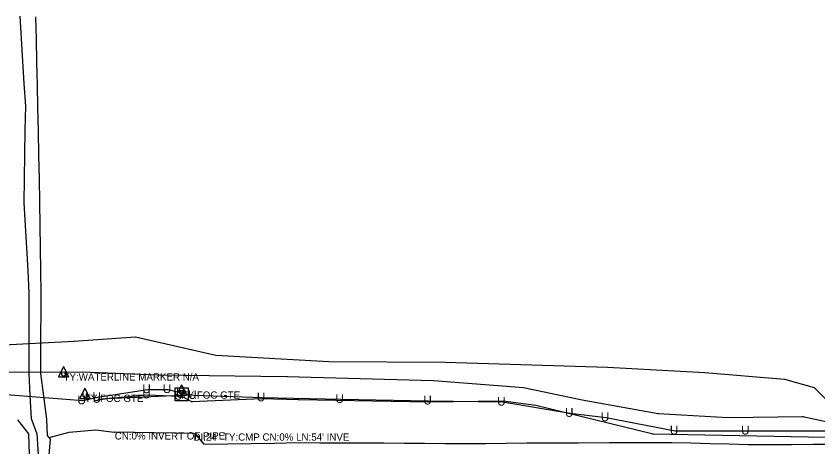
# Model space of a CAD drawing. Extents: x 1800653 to 1804042, y 522635 to 523313.
# Drawn here: x 1802247 to 1802797, y 523018 to 523313 of the extents above; entities that cross this region are included whole.
import ezdxf

# ---------------------------------------------------------------- set-up
doc = ezdxf.new("R2010")
doc.units = 0
for name, color, linetype in [('Default', 7, 'Continuous'), ('S_DITCHLINE', 7, 'Continuous'), ('S_DRG_PT_SYM', 7, 'Continuous'), ('S_FIBER_OPTIC_CABLE', 7, 'Continuous'), ('S_GAS_UTILITIES', 7, 'Continuous'), ('S_SIDE_DRAIN', 7, 'Continuous'), ('S_SIDE_DRAIN_ANNOT', 7, 'Continuous'), ('S_STREAM', 7, 'Continuous'), ('S_TELEPHONE_UTILITIES', 7, 'Continuous'), ('S_UNDERGROUND_CABLE', 7, 'Continuous'), ('S_UTILITY_POLE_ANNOT', 7, 'Continuous'), ('S_UTL_PT_SYM', 7, 'Continuous'), ('S_WATER_UTILITIES', 7, 'Continuous')]:
    doc.layers.add(name, color=color, linetype=linetype)

msp = doc.modelspace()

# ---------------------------------------------------------------- linework, layer by layer
at = {"layer": 'S_DITCHLINE'}
for points in [[(1802269.66, 523024.43), (1802283.4, 523028.06), (1802301.66, 523029.67), (1802314.11, 523027.91)], [(1802369.25, 523027.2), (1802375.66, 523019.66), (1802391.84, 523019.94), (1802408.03, 523020.23), (1802424.22, 523020.51), (1802440.41, 523020.79), (1802455.09, 523020.75), (1802469.77, 523020.7), (1802484.45, 523020.66), (1802499.13, 523020.61), (1802513.07, 523020.5), (1802527.01, 523020.39), (1802540.96, 523020.28), (1802554.9, 523020.18), (1802568.97, 523020.3), (1802583.04, 523020.43), (1802597.12, 523020.56), (1802611.19, 523020.69), (1802632.52, 523020.74), (1802653.86, 523020.8), (1802675.19, 523020.85), (1802696.52, 523020.91), (1802709.66, 523020.57), (1802722.79, 523020.22), (1802735.93, 523019.88), (1802749.06, 523019.54), (1802763.84, 523019.58), (1802778.62, 523019.62), (1802793.4, 523019.66), (1802808.18, 523019.7)]]:
    msp.add_lwpolyline(points, dxfattribs=at)
at = {"layer": 'S_DRG_PT_SYM'}
for points in [[(1802314.54, 523027.95), (1802314.54, 523028), (1802314.54, 523027.95), (1802314.49, 523027.95), (1802314.54, 523027.95), (1802314.54, 523027.9), (1802314.54, 523027.95), (1802314.59, 523027.95)], [(1802368.56, 523027.13), (1802368.56, 523027.18), (1802368.56, 523027.13), (1802368.51, 523027.13), (1802368.56, 523027.13), (1802368.56, 523027.08), (1802368.56, 523027.13), (1802368.61, 523027.13)]]:
    msp.add_lwpolyline(points, dxfattribs=at)
at = {"layer": 'S_FIBER_OPTIC_CABLE'}
for p, q in [((1802309.12, 523050.85), (1802303.42, 523049.88)), ((1802349.78, 523052.63), (1802309.12, 523050.85)), ((1802359.84, 523052.9), (1802349.78, 523052.63)), ((1802367.52, 523048.71), (1802359.84, 523052.9)), ((1802415.11, 523050.82), (1802367.52, 523048.71)), ((1802440.73, 523050.19), (1802415.11, 523050.82)), ((1802529.47, 523048.64), (1802440.73, 523050.19)), ((1802580.88, 523049.27), (1802529.47, 523048.64)), ((1802603.36, 523046.35), (1802580.88, 523049.27)), ((1802683.7, 523026.61), (1802603.36, 523046.35)), ((1802802.2, 523024.23), (1802683.7, 523026.61))]:
    msp.add_line(p, q, dxfattribs=at)
at = {"layer": 'S_GAS_UTILITIES'}
for p, q in [((1802220.06, 523086.97), (1802286.56, 523090.26)), ((1802286.56, 523090.26), (1802328.86, 523093.33)), ((1802328.86, 523093.33), (1802383.84, 523080.76)), ((1802383.84, 523080.76), (1802461.37, 523076.34)), ((1802461.37, 523076.34), (1802541.11, 523075.84)), ((1802541.11, 523075.84), (1802652.53, 523072.49)), ((1802652.53, 523072.49), (1802719.3, 523068.84)), ((1802719.3, 523068.84), (1802773.94, 523064.21)), ((1802773.94, 523064.21), (1802794.31, 523058.67)), ((1802794.31, 523058.67), (1802806.01, 523046.72))]:
    msp.add_line(p, q, dxfattribs=at)
at = {"layer": 'S_SIDE_DRAIN'}
msp.add_line((1802368.56, 523027.13), (1802314.54, 523027.95), dxfattribs=at)
at = {"layer": 'S_STREAM'}
for points in [[(1802249.41, 523313.08), (1802250.37, 523297.65), (1802251.32, 523282.22), (1802252.27, 523266.78), (1802253.23, 523251.35), (1802252.98, 523234.78), (1802252.74, 523218.21), (1802252.5, 523201.64), (1802252.26, 523185.07), (1802253.13, 523169.63), (1802254, 523154.19), (1802254.87, 523138.75), (1802255.74, 523123.32), (1802255.71, 523109.58), (1802255.69, 523095.84), (1802255.67, 523082.1), (1802255.65, 523068.37), (1802256.4, 523052.81), (1802257.15, 523037.26), (1802261.21, 523026.93), (1802262, 523012.39)], [(1802260.22, 523312.47), (1802260.58, 523296.96), (1802260.94, 523281.44), (1802261.29, 523265.92), (1802261.65, 523250.4), (1802261.98, 523234.11), (1802262.31, 523217.81), (1802262.64, 523201.52), (1802262.97, 523185.22), (1802263.18, 523169.68), (1802263.39, 523154.14), (1802263.59, 523138.6), (1802263.8, 523123.06), (1802263.75, 523109.33), (1802263.71, 523095.6), (1802263.66, 523081.86), (1802263.62, 523068.13), (1802265.62, 523052.55), (1802267.63, 523036.97), (1802268.3, 523025.72), (1802270.16, 523023.24), (1802269.12, 523009.76)], [(1802247.74, 523036.5), (1802255.39, 523026.86), (1802255.81, 523012.78), (1802256.24, 522998.7), (1802253.02, 522982.1), (1802249.81, 522965.5), (1802248.85, 522942.84), (1802247.89, 522920.18)]]:
    msp.add_lwpolyline(points, dxfattribs=at)
at = {"layer": 'S_TELEPHONE_UTILITIES'}
msp.add_lwpolyline([(1802356.01, 523049.36), (1802356.01, 523058.36), (1802365.01, 523058.36), (1802365.01, 523049.36)], close=True, dxfattribs=at)
at = {"layer": 'S_UNDERGROUND_CABLE'}
for p, q in [((1802279.43, 523072.91), (1802275.91, 523065.82)), ((1802279.43, 523072.91), (1802282.92, 523065.82)), ((1802278.23, 523067.06), (1802278.23, 523069.5)), ((1802278.85, 523066.4), (1802278.23, 523067.06)), ((1802280.05, 523066.4), (1802278.85, 523066.4)), ((1802280.6, 523067.06), (1802280.05, 523066.4)), ((1802280.6, 523069.5), (1802280.6, 523067.06)), ((1802275.91, 523065.82), (1802282.92, 523065.82)), ((1802213.99, 523055.95), (1802292.61, 523049.61)), ((1802294.06, 523058.2), (1802290.54, 523051.11)), ((1802294.06, 523058.2), (1802297.55, 523051.11)), ((1802302.89, 523051.9), (1802337.09, 523057.26)), ((1802337.09, 523057.26), (1802351.14, 523057.32)), ((1802351.14, 523057.32), (1802360.25, 523054.82)), ((1802360.44, 523060.44), (1802356.91, 523053.35)), ((1802359.24, 523054.59), (1802359.24, 523057.03)), ((1802360.44, 523060.44), (1802363.93, 523053.35)), ((1802361.6, 523057.03), (1802361.6, 523054.59)), ((1802290.54, 523051.11), (1802297.55, 523051.11)), ((1802292.61, 523049.61), (1802302.89, 523051.9)), ((1802292.86, 523052.35), (1802292.86, 523054.79)), ((1802293.48, 523051.69), (1802292.86, 523052.35)), ((1802294.68, 523051.69), (1802293.48, 523051.69)), ((1802295.23, 523052.35), (1802294.68, 523051.69)), ((1802295.23, 523054.79), (1802295.23, 523052.35)), ((1802302.98, 523050.67), (1802337.06, 523053.66)), ((1802337.06, 523053.66), (1802358.84, 523052.74)), ((1802356.91, 523053.35), (1802363.93, 523053.35)), ((1802358.84, 523052.74), (1802360.29, 523054.06)), ((1802359.86, 523053.93), (1802359.24, 523054.59)), ((1802361.06, 523053.93), (1802359.86, 523053.93)), ((1802360.25, 523054.82), (1802368.48, 523053.29)), ((1802361.6, 523054.59), (1802361.06, 523053.93)), ((1802368.48, 523053.29), (1802415.64, 523051.63)), ((1802415.64, 523051.63), (1802469.54, 523050.51)), ((1802469.54, 523050.51), (1802529.81, 523049.5)), ((1802529.81, 523049.5), (1802580.45, 523048.71)), ((1802580.45, 523048.71), (1802626.98, 523041.02)), ((1802626.98, 523041.02), (1802651.55, 523038.01)), ((1802651.55, 523038.01), (1802698.92, 523028.86)), ((1802698.92, 523028.86), (1802747.76, 523028.88)), ((1802747.76, 523028.88), (1802802.31, 523028.93))]:
    msp.add_line(p, q, dxfattribs=at)
at = {"layer": 'S_UTL_PT_SYM'}
for points in [[(1802286.56, 523090.26), (1802286.56, 523090.31), (1802286.56, 523090.26), (1802286.51, 523090.26), (1802286.56, 523090.26), (1802286.56, 523090.21), (1802286.56, 523090.26), (1802286.61, 523090.26)], [(1802328.86, 523093.33), (1802328.86, 523093.38), (1802328.86, 523093.33), (1802328.81, 523093.33), (1802328.86, 523093.33), (1802328.86, 523093.28), (1802328.86, 523093.33), (1802328.91, 523093.33)], [(1802383.84, 523080.76), (1802383.84, 523080.81), (1802383.84, 523080.76), (1802383.79, 523080.76), (1802383.84, 523080.76), (1802383.84, 523080.71), (1802383.84, 523080.76), (1802383.89, 523080.76)], [(1802461.37, 523076.34), (1802461.37, 523076.39), (1802461.37, 523076.34), (1802461.32, 523076.34), (1802461.37, 523076.34), (1802461.37, 523076.29), (1802461.37, 523076.34), (1802461.42, 523076.34)], [(1802541.11, 523075.84), (1802541.11, 523075.89), (1802541.11, 523075.84), (1802541.06, 523075.84), (1802541.11, 523075.84), (1802541.11, 523075.79), (1802541.11, 523075.84), (1802541.16, 523075.84)], [(1802652.53, 523072.49), (1802652.53, 523072.54), (1802652.53, 523072.49), (1802652.48, 523072.49), (1802652.53, 523072.49), (1802652.53, 523072.44), (1802652.53, 523072.49), (1802652.58, 523072.49)], [(1802292.52, 523069.23), (1802292.52, 523069.28), (1802292.52, 523069.23), (1802292.47, 523069.23), (1802292.52, 523069.23), (1802292.52, 523069.18), (1802292.52, 523069.23), (1802292.57, 523069.23)], [(1802343.69, 523067.27), (1802343.69, 523067.32), (1802343.69, 523067.27), (1802343.64, 523067.27), (1802343.69, 523067.27), (1802343.69, 523067.22), (1802343.69, 523067.27), (1802343.74, 523067.27)], [(1802343.71, 523067.26), (1802343.71, 523067.31), (1802343.71, 523067.26), (1802343.66, 523067.26), (1802343.71, 523067.26), (1802343.71, 523067.21), (1802343.71, 523067.26), (1802343.76, 523067.26)], [(1802719.3, 523068.84), (1802719.3, 523068.89), (1802719.3, 523068.84), (1802719.25, 523068.84), (1802719.3, 523068.84), (1802719.3, 523068.79), (1802719.3, 523068.84), (1802719.35, 523068.84)], [(1802432.55, 523066.19), (1802432.55, 523066.24), (1802432.55, 523066.19), (1802432.5, 523066.19), (1802432.55, 523066.19), (1802432.55, 523066.14), (1802432.55, 523066.19), (1802432.6, 523066.19)], [(1802533.24, 523063.3), (1802533.24, 523063.35), (1802533.24, 523063.3), (1802533.19, 523063.3), (1802533.24, 523063.3), (1802533.24, 523063.25), (1802533.24, 523063.3), (1802533.29, 523063.3)], [(1802773.94, 523064.21), (1802773.94, 523064.26), (1802773.94, 523064.21), (1802773.89, 523064.21), (1802773.94, 523064.21), (1802773.94, 523064.16), (1802773.94, 523064.21), (1802773.99, 523064.21)], [(1802594.91, 523058.64), (1802594.91, 523058.69), (1802594.91, 523058.64), (1802594.86, 523058.64), (1802594.91, 523058.64), (1802594.91, 523058.59), (1802594.91, 523058.64), (1802594.96, 523058.64)], [(1802794.31, 523058.67), (1802794.31, 523058.72), (1802794.31, 523058.67), (1802794.26, 523058.67), (1802794.31, 523058.67), (1802794.31, 523058.62), (1802794.31, 523058.67), (1802794.36, 523058.67)], [(1802303.42, 523049.88), (1802303.42, 523049.93), (1802303.42, 523049.88), (1802303.37, 523049.88), (1802303.42, 523049.88), (1802303.42, 523049.83), (1802303.42, 523049.88), (1802303.47, 523049.88)], [(1802309.12, 523050.85), (1802309.12, 523050.9), (1802309.12, 523050.85), (1802309.07, 523050.85), (1802309.12, 523050.85), (1802309.12, 523050.8), (1802309.12, 523050.85), (1802309.17, 523050.85)], [(1802349.78, 523052.63), (1802349.78, 523052.68), (1802349.78, 523052.63), (1802349.73, 523052.63), (1802349.78, 523052.63), (1802349.78, 523052.58), (1802349.78, 523052.63), (1802349.83, 523052.63)], [(1802359.84, 523052.9), (1802359.84, 523052.95), (1802359.84, 523052.9), (1802359.79, 523052.9), (1802359.84, 523052.9), (1802359.84, 523052.85), (1802359.84, 523052.9), (1802359.89, 523052.9)], [(1802415.11, 523050.82), (1802415.11, 523050.87), (1802415.11, 523050.82), (1802415.06, 523050.82), (1802415.11, 523050.82), (1802415.11, 523050.77), (1802415.11, 523050.82), (1802415.16, 523050.82)], [(1802440.73, 523050.19), (1802440.73, 523050.24), (1802440.73, 523050.19), (1802440.68, 523050.19), (1802440.73, 523050.19), (1802440.73, 523050.14), (1802440.73, 523050.19), (1802440.78, 523050.19)], [(1802635.1, 523050.19), (1802635.1, 523050.24), (1802635.1, 523050.19), (1802635.05, 523050.19), (1802635.1, 523050.19), (1802635.1, 523050.14), (1802635.1, 523050.19), (1802635.15, 523050.19)], [(1802367.52, 523048.71), (1802367.52, 523048.76), (1802367.52, 523048.71), (1802367.47, 523048.71), (1802367.52, 523048.71), (1802367.52, 523048.66), (1802367.52, 523048.71), (1802367.57, 523048.71)], [(1802529.47, 523048.64), (1802529.47, 523048.69), (1802529.47, 523048.64), (1802529.42, 523048.64), (1802529.47, 523048.64), (1802529.47, 523048.59), (1802529.47, 523048.64), (1802529.52, 523048.64)], [(1802580.88, 523049.27), (1802580.88, 523049.32), (1802580.88, 523049.27), (1802580.83, 523049.27), (1802580.88, 523049.27), (1802580.88, 523049.22), (1802580.88, 523049.27), (1802580.93, 523049.27)], [(1802603.36, 523046.35), (1802603.36, 523046.4), (1802603.36, 523046.35), (1802603.31, 523046.35), (1802603.36, 523046.35), (1802603.36, 523046.3), (1802603.36, 523046.35), (1802603.41, 523046.35)], [(1802687.34, 523040.86), (1802687.34, 523040.91), (1802687.34, 523040.86), (1802687.29, 523040.86), (1802687.34, 523040.86), (1802687.34, 523040.81), (1802687.34, 523040.86), (1802687.39, 523040.86)], [(1802786.43, 523038.78), (1802786.43, 523038.83), (1802786.43, 523038.78), (1802786.38, 523038.78), (1802786.43, 523038.78), (1802786.43, 523038.73), (1802786.43, 523038.78), (1802786.48, 523038.78)], [(1802735.26, 523038.05), (1802735.26, 523038.1), (1802735.26, 523038.05), (1802735.21, 523038.05), (1802735.26, 523038.05), (1802735.26, 523038), (1802735.26, 523038.05), (1802735.31, 523038.05)], [(1802683.7, 523026.61), (1802683.7, 523026.66), (1802683.7, 523026.61), (1802683.65, 523026.61), (1802683.7, 523026.61), (1802683.7, 523026.56), (1802683.7, 523026.61), (1802683.75, 523026.61)]]:
    msp.add_lwpolyline(points, dxfattribs=at)
at = {"layer": 'S_WATER_UTILITIES'}
for p, q in [((1802220.95, 523069), (1802292.52, 523069.23)), ((1802292.52, 523069.23), (1802343.69, 523067.27)), ((1802343.69, 523067.27), (1802343.71, 523067.26)), ((1802343.71, 523067.26), (1802432.55, 523066.19)), ((1802432.55, 523066.19), (1802533.24, 523063.3)), ((1802533.24, 523063.3), (1802594.91, 523058.64)), ((1802594.91, 523058.64), (1802635.1, 523050.19)), ((1802635.1, 523050.19), (1802687.34, 523040.86)), ((1802687.34, 523040.86), (1802735.26, 523038.05)), ((1802735.26, 523038.05), (1802786.43, 523038.78)), ((1802786.43, 523038.78), (1802812.37, 523032.99))]:
    msp.add_line(p, q, dxfattribs=at)

# ---------------------------------------------------------------- texts
at = {"layer": 'Default'}
for p in [(1802299.26, 523049.35), (1802333.43, 523051.11), (1802333.46, 523054.72), (1802347.51, 523054.77), (1802355.21, 523050.2), (1802356.62, 523052.27), (1802356.66, 523051.52), (1802364.85, 523050.74), (1802288.98, 523047.06), (1802299.35, 523048.12), (1802412.01, 523049.08), (1802465.91, 523047.96), (1802526.18, 523046.96), (1802576.82, 523046.16), (1802623.35, 523038.48), (1802647.92, 523035.47), (1802695.29, 523026.32), (1802744.13, 523026.34)]:
    msp.add_text('U', height=6, dxfattribs=at).set_placement(p)
at = {"layer": 'S_SIDE_DRAIN_ANNOT'}
for s, p in [('CN:0% INVERT OF PIPE', (1802314.54, 523022.95)), ('DI:24" TY:CMP CN:0% LN:54\' INVE', (1802368.56, 523022.13))]:
    msp.add_text(s, height=5, dxfattribs=at).set_placement(p)
at = {"layer": 'S_TELEPHONE_UTILITIES'}
msp.add_text('T', height=6, dxfattribs=at).set_placement((1802358.57, 523050.86))
at = {"layer": 'S_UTILITY_POLE_ANNOT'}
for s, p in [('TY:WATERLINE MARKER N/A', (1802279.43, 523063.37)), ('TY:FOC GTE', (1802360.44, 523050.91)), ('TY:FOC GTE', (1802294.06, 523048.67))]:
    msp.add_text(s, height=5, dxfattribs=at).set_placement(p)

doc.saveas('drawing.dxf')
